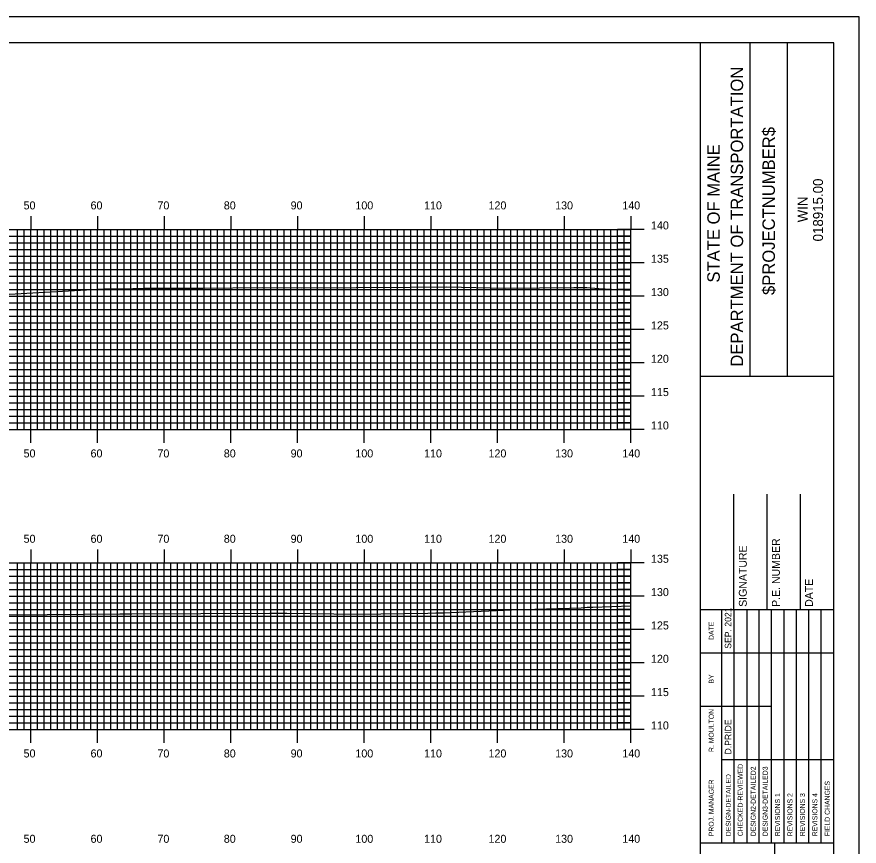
# Model space of a CAD drawing. Extents: x 852540 to 852884, y 364661 to 364881.
# Drawn here: x 852754.2 to 852880.5, y 364756.9 to 364881.3 of the extents above; entities that cross this region are included whole.
import ezdxf

# ---------------------------------------------------------------- set-up
doc = ezdxf.new("R2010")
doc.units = 0
for name, color, linetype in [('BORDER', 7, 'Continuous'), ('H_V ANNOTATION', 7, 'Continuous'), ('MAJOR', 7, 'Continuous'), ('MINOR', 7, 'Continuous'), ('PLOT BOUNDARY', 7, 'Continuous'), ('S_Roadway_Centerline', 7, 'Continuous')]:
    doc.layers.add(name, color=color, linetype=linetype)

msp = doc.modelspace()

# ---------------------------------------------------------------- linework, layer by layer
at = {"layer": 'BORDER'}
for p, q in [((852856.67, 364667.37), (852856.67, 364877.37)), ((852864.13, 364827.36), (852864.13, 364877.36)), ((852869.72, 364827.36), (852869.72, 364877.36)), ((852856.67, 364827.36), (852876.67, 364827.36)), ((852861.67, 364792.38), (852861.67, 364809.67)), ((852866.67, 364792.38), (852866.67, 364809.67)), ((852871.67, 364792.38), (852871.67, 364809.67)), ((852856.67, 364792.38), (852876.67, 364792.38)), ((852856.67, 364757.38), (852876.67, 364757.38)), ((852867.85, 364687.38), (852867.85, 364757.38))]:
    msp.add_line(p, q, dxfattribs=at)
msp.add_lwpolyline([(852556.67, 364667.37), (852876.67, 364667.37), (852876.67, 364877.37), (852556.67, 364877.37)], close=True, dxfattribs=at)
for points in [[(852859.9, 364785.88), (852859.9, 364792.38)], [(852861.76, 364757.38), (852861.76, 364792.38)], [(852863.63, 364792.38), (852863.63, 364757.38)], [(852865.49, 364757.38), (852865.49, 364792.38)], [(852867.35, 364757.38), (852867.35, 364792.38)], [(852869.22, 364757.38), (852869.22, 364792.38)], [(852871.08, 364757.38), (852871.08, 364792.38)], [(852872.94, 364757.38), (852872.94, 364792.38)], [(852874.81, 364757.38), (852874.81, 364792.38)], [(852859.9, 364757.38), (852859.9, 364790.96)], [(852856.67, 364785.88), (852876.67, 364785.88)], [(852856.67, 364777.88), (852859.9, 364777.88)], [(852859.9, 364777.88), (852867.35, 364777.88)], [(852859.9, 364769.88), (852876.67, 364769.88)]]:
    msp.add_lwpolyline(points, dxfattribs=at)
at = {"layer": 'MAJOR'}
for p, q in [((852756.27, 364851.37), (852756.27, 364849.37)), ((852766.27, 364851.37), (852766.27, 364849.37)), ((852776.27, 364851.37), (852776.27, 364849.37)), ((852786.27, 364851.37), (852786.27, 364849.37)), ((852796.27, 364851.37), (852796.27, 364849.37)), ((852806.27, 364851.37), (852806.27, 364849.37)), ((852816.27, 364851.37), (852816.27, 364849.37)), ((852826.27, 364851.37), (852826.27, 364849.37)), ((852836.27, 364851.37), (852836.27, 364849.37)), ((852846.27, 364851.37), (852846.27, 364849.37)), ((852566.27, 364849.37), (852846.27, 364849.37)), ((852566.27, 364849.37), (852846.27, 364849.37)), ((852756.27, 364819.37), (852756.27, 364849.37)), ((852766.27, 364819.37), (852766.27, 364849.37)), ((852776.27, 364819.37), (852776.27, 364849.37)), ((852786.27, 364819.37), (852786.27, 364849.37)), ((852796.27, 364819.37), (852796.27, 364849.37)), ((852806.27, 364819.37), (852806.27, 364849.37)), ((852816.27, 364819.37), (852816.27, 364849.37)), ((852826.27, 364819.37), (852826.27, 364849.37)), ((852836.27, 364819.37), (852836.27, 364849.37)), ((852848.27, 364849.37), (852844.26, 364849.37)), ((852846.27, 364819.37), (852846.27, 364849.37)), ((852846.27, 364819.37), (852846.27, 364849.37)), ((852566.27, 364844.37), (852846.27, 364844.37)), ((852848.27, 364844.37), (852844.26, 364844.37)), ((852566.27, 364839.37), (852846.27, 364839.37)), ((852848.27, 364839.37), (852844.26, 364839.37)), ((852566.27, 364834.37), (852846.27, 364834.37)), ((852848.27, 364834.37), (852844.26, 364834.37)), ((852566.27, 364829.37), (852846.27, 364829.37)), ((852848.27, 364829.37), (852844.26, 364829.37)), ((852566.27, 364824.37), (852846.27, 364824.37)), ((852848.27, 364824.37), (852844.26, 364824.37)), ((852566.27, 364819.37), (852846.27, 364819.37)), ((852566.27, 364819.37), (852846.27, 364819.37)), ((852756.27, 364817.37), (852756.27, 364819.37)), ((852766.27, 364817.37), (852766.27, 364819.37)), ((852776.27, 364817.37), (852776.27, 364819.37)), ((852786.27, 364817.37), (852786.27, 364819.37)), ((852796.27, 364817.37), (852796.27, 364819.37)), ((852806.27, 364817.37), (852806.27, 364819.37)), ((852816.27, 364817.37), (852816.27, 364819.37)), ((852826.27, 364817.37), (852826.27, 364819.37)), ((852836.27, 364817.37), (852836.27, 364819.37)), ((852848.27, 364819.37), (852844.26, 364819.37)), ((852846.27, 364817.37), (852846.27, 364819.37)), ((852756.27, 364801.37), (852756.27, 364799.37)), ((852766.27, 364801.37), (852766.27, 364799.37)), ((852776.27, 364801.37), (852776.27, 364799.37)), ((852786.27, 364801.37), (852786.27, 364799.37)), ((852796.27, 364801.37), (852796.27, 364799.37)), ((852806.27, 364801.37), (852806.27, 364799.37)), ((852816.27, 364801.37), (852816.27, 364799.37)), ((852826.27, 364801.37), (852826.27, 364799.37)), ((852836.27, 364801.37), (852836.27, 364799.37)), ((852846.27, 364801.37), (852846.27, 364799.37)), ((852566.27, 364799.37), (852846.27, 364799.37)), ((852566.27, 364799.37), (852846.27, 364799.37)), ((852756.27, 364774.37), (852756.27, 364799.37)), ((852766.27, 364774.37), (852766.27, 364799.37)), ((852776.27, 364774.37), (852776.27, 364799.37)), ((852786.27, 364774.37), (852786.27, 364799.37)), ((852796.27, 364774.37), (852796.27, 364799.37)), ((852806.27, 364774.37), (852806.27, 364799.37)), ((852816.27, 364774.37), (852816.27, 364799.37)), ((852826.27, 364774.37), (852826.27, 364799.37)), ((852836.27, 364774.37), (852836.27, 364799.37)), ((852848.27, 364799.37), (852844.26, 364799.37)), ((852846.27, 364774.37), (852846.27, 364799.37)), ((852846.27, 364774.37), (852846.27, 364799.37)), ((852566.27, 364794.37), (852846.27, 364794.37)), ((852848.27, 364794.37), (852844.26, 364794.37)), ((852566.27, 364789.37), (852846.27, 364789.37)), ((852848.27, 364789.37), (852844.26, 364789.37)), ((852566.27, 364784.37), (852846.27, 364784.37)), ((852848.27, 364784.37), (852844.26, 364784.37)), ((852566.27, 364779.37), (852846.27, 364779.37)), ((852848.27, 364779.37), (852844.26, 364779.37)), ((852566.27, 364774.37), (852846.27, 364774.37)), ((852566.27, 364774.37), (852846.27, 364774.37)), ((852756.27, 364772.37), (852756.27, 364774.37)), ((852766.27, 364772.37), (852766.27, 364774.37)), ((852776.27, 364772.37), (852776.27, 364774.37)), ((852786.27, 364772.37), (852786.27, 364774.37)), ((852796.27, 364772.37), (852796.27, 364774.37)), ((852806.27, 364772.37), (852806.27, 364774.37)), ((852816.27, 364772.37), (852816.27, 364774.37)), ((852826.27, 364772.37), (852826.27, 364774.37)), ((852836.27, 364772.37), (852836.27, 364774.37)), ((852848.27, 364774.37), (852844.26, 364774.37)), ((852846.27, 364772.37), (852846.27, 364774.37))]:
    msp.add_line(p, q, dxfattribs=at)
at = {"layer": 'MINOR'}
for p, q in [((852754.27, 364819.37), (852754.27, 364849.37)), ((852755.27, 364819.37), (852755.27, 364849.37)), ((852757.27, 364819.37), (852757.27, 364849.37)), ((852758.27, 364819.37), (852758.27, 364849.37)), ((852759.27, 364819.37), (852759.27, 364849.37)), ((852760.27, 364819.37), (852760.27, 364849.37)), ((852761.27, 364819.37), (852761.27, 364849.37)), ((852762.27, 364819.37), (852762.27, 364849.37)), ((852763.27, 364819.37), (852763.27, 364849.37)), ((852764.27, 364819.37), (852764.27, 364849.37)), ((852765.27, 364819.37), (852765.27, 364849.37)), ((852767.27, 364819.37), (852767.27, 364849.37)), ((852768.27, 364819.37), (852768.27, 364849.37)), ((852769.27, 364819.37), (852769.27, 364849.37)), ((852770.27, 364819.37), (852770.27, 364849.37)), ((852771.27, 364819.37), (852771.27, 364849.37)), ((852772.27, 364819.37), (852772.27, 364849.37)), ((852773.27, 364819.37), (852773.27, 364849.37)), ((852774.27, 364819.37), (852774.27, 364849.37)), ((852775.27, 364819.37), (852775.27, 364849.37)), ((852777.27, 364819.37), (852777.27, 364849.37)), ((852778.27, 364819.37), (852778.27, 364849.37)), ((852779.27, 364819.37), (852779.27, 364849.37)), ((852780.27, 364819.37), (852780.27, 364849.37)), ((852781.27, 364819.37), (852781.27, 364849.37)), ((852782.27, 364819.37), (852782.27, 364849.37)), ((852783.27, 364819.37), (852783.27, 364849.37)), ((852784.27, 364819.37), (852784.27, 364849.37)), ((852785.27, 364819.37), (852785.27, 364849.37)), ((852787.27, 364819.37), (852787.27, 364849.37)), ((852788.27, 364819.37), (852788.27, 364849.37)), ((852789.27, 364819.37), (852789.27, 364849.37)), ((852790.27, 364819.37), (852790.27, 364849.37)), ((852791.27, 364819.37), (852791.27, 364849.37)), ((852792.27, 364819.37), (852792.27, 364849.37)), ((852793.27, 364819.37), (852793.27, 364849.37)), ((852794.27, 364819.37), (852794.27, 364849.37)), ((852795.27, 364819.37), (852795.27, 364849.37)), ((852797.27, 364819.37), (852797.27, 364849.37)), ((852798.27, 364819.37), (852798.27, 364849.37)), ((852799.27, 364819.37), (852799.27, 364849.37)), ((852800.27, 364819.37), (852800.27, 364849.37)), ((852801.27, 364819.37), (852801.27, 364849.37)), ((852802.27, 364819.37), (852802.27, 364849.37)), ((852803.27, 364819.37), (852803.27, 364849.37)), ((852804.27, 364819.37), (852804.27, 364849.37)), ((852805.27, 364819.37), (852805.27, 364849.37)), ((852807.27, 364819.37), (852807.27, 364849.37)), ((852808.27, 364819.37), (852808.27, 364849.37)), ((852809.27, 364819.37), (852809.27, 364849.37)), ((852810.27, 364819.37), (852810.27, 364849.37)), ((852811.27, 364819.37), (852811.27, 364849.37)), ((852812.27, 364819.37), (852812.27, 364849.37)), ((852813.27, 364819.37), (852813.27, 364849.37)), ((852814.27, 364819.37), (852814.27, 364849.37)), ((852815.27, 364819.37), (852815.27, 364849.37)), ((852817.27, 364819.37), (852817.27, 364849.37)), ((852818.27, 364819.37), (852818.27, 364849.37)), ((852819.27, 364819.37), (852819.27, 364849.37)), ((852820.27, 364819.37), (852820.27, 364849.37)), ((852821.27, 364819.37), (852821.27, 364849.37)), ((852822.27, 364819.37), (852822.27, 364849.37)), ((852823.27, 364819.37), (852823.27, 364849.37)), ((852824.27, 364819.37), (852824.27, 364849.37)), ((852825.27, 364819.37), (852825.27, 364849.37)), ((852827.27, 364819.37), (852827.27, 364849.37)), ((852828.27, 364819.37), (852828.27, 364849.37)), ((852829.27, 364819.37), (852829.27, 364849.37)), ((852830.27, 364819.37), (852830.27, 364849.37)), ((852831.27, 364819.37), (852831.27, 364849.37)), ((852832.27, 364819.37), (852832.27, 364849.37)), ((852833.27, 364819.37), (852833.27, 364849.37)), ((852834.27, 364819.37), (852834.27, 364849.37)), ((852835.27, 364819.37), (852835.27, 364849.37)), ((852837.27, 364819.37), (852837.27, 364849.37)), ((852838.27, 364819.37), (852838.27, 364849.37)), ((852839.27, 364819.37), (852839.27, 364849.37)), ((852840.27, 364819.37), (852840.27, 364849.37)), ((852841.27, 364819.37), (852841.27, 364849.37)), ((852842.27, 364819.37), (852842.27, 364849.37)), ((852843.27, 364819.37), (852843.27, 364849.37)), ((852844.27, 364819.37), (852844.27, 364849.37)), ((852845.27, 364819.37), (852845.27, 364849.37)), ((852566.27, 364848.37), (852846.27, 364848.37)), ((852846.27, 364848.37), (852844.26, 364848.37)), ((852566.27, 364847.37), (852846.27, 364847.37)), ((852846.27, 364847.37), (852844.26, 364847.37)), ((852566.27, 364846.37), (852846.27, 364846.37)), ((852846.27, 364846.37), (852844.26, 364846.37)), ((852566.27, 364845.37), (852846.27, 364845.37)), ((852846.27, 364845.37), (852844.26, 364845.37)), ((852566.27, 364843.37), (852846.27, 364843.37)), ((852846.27, 364843.37), (852844.26, 364843.37)), ((852566.27, 364842.37), (852846.27, 364842.37)), ((852846.27, 364842.37), (852844.26, 364842.37)), ((852566.27, 364841.37), (852846.27, 364841.37)), ((852846.27, 364841.37), (852844.26, 364841.37)), ((852566.27, 364840.37), (852846.27, 364840.37)), ((852846.27, 364840.37), (852844.26, 364840.37)), ((852566.27, 364838.37), (852846.27, 364838.37)), ((852846.27, 364838.37), (852844.26, 364838.37)), ((852566.27, 364837.37), (852846.27, 364837.37)), ((852846.27, 364837.37), (852844.26, 364837.37)), ((852566.27, 364836.37), (852846.27, 364836.37)), ((852846.27, 364836.37), (852844.26, 364836.37)), ((852566.27, 364835.37), (852846.27, 364835.37)), ((852846.27, 364835.37), (852844.26, 364835.37)), ((852566.27, 364833.37), (852846.27, 364833.37)), ((852846.27, 364833.37), (852844.26, 364833.37)), ((852566.27, 364832.37), (852846.27, 364832.37)), ((852846.27, 364832.37), (852844.26, 364832.37)), ((852566.27, 364831.37), (852846.27, 364831.37)), ((852846.27, 364831.37), (852844.26, 364831.37)), ((852566.27, 364830.37), (852846.27, 364830.37)), ((852846.27, 364830.37), (852844.26, 364830.37)), ((852566.27, 364828.37), (852846.27, 364828.37)), ((852846.27, 364828.37), (852844.26, 364828.37)), ((852566.27, 364827.37), (852846.27, 364827.37)), ((852846.27, 364827.37), (852844.26, 364827.37)), ((852566.27, 364826.37), (852846.27, 364826.37)), ((852566.27, 364825.37), (852846.27, 364825.37)), ((852846.27, 364826.37), (852844.26, 364826.37)), ((852846.27, 364825.37), (852844.26, 364825.37)), ((852566.27, 364823.37), (852846.27, 364823.37)), ((852846.27, 364823.37), (852844.26, 364823.37)), ((852566.27, 364822.37), (852846.27, 364822.37)), ((852846.27, 364822.37), (852844.26, 364822.37)), ((852566.27, 364821.37), (852846.27, 364821.37)), ((852566.27, 364820.37), (852846.27, 364820.37)), ((852846.27, 364821.37), (852844.26, 364821.37)), ((852846.27, 364820.37), (852844.26, 364820.37)), ((852754.27, 364774.37), (852754.27, 364799.37)), ((852755.27, 364774.37), (852755.27, 364799.37)), ((852757.27, 364774.37), (852757.27, 364799.37)), ((852758.27, 364774.37), (852758.27, 364799.37)), ((852759.27, 364774.37), (852759.27, 364799.37)), ((852760.27, 364774.37), (852760.27, 364799.37)), ((852761.27, 364774.37), (852761.27, 364799.37)), ((852762.27, 364774.37), (852762.27, 364799.37)), ((852763.27, 364774.37), (852763.27, 364799.37)), ((852764.27, 364774.37), (852764.27, 364799.37)), ((852765.27, 364774.37), (852765.27, 364799.37)), ((852767.27, 364774.37), (852767.27, 364799.37)), ((852768.27, 364774.37), (852768.27, 364799.37)), ((852769.27, 364774.37), (852769.27, 364799.37)), ((852770.27, 364774.37), (852770.27, 364799.37)), ((852771.27, 364774.37), (852771.27, 364799.37)), ((852772.27, 364774.37), (852772.27, 364799.37)), ((852773.27, 364774.37), (852773.27, 364799.37)), ((852774.27, 364774.37), (852774.27, 364799.37)), ((852775.27, 364774.37), (852775.27, 364799.37)), ((852777.27, 364774.37), (852777.27, 364799.37)), ((852778.27, 364774.37), (852778.27, 364799.37)), ((852779.27, 364774.37), (852779.27, 364799.37)), ((852780.27, 364774.37), (852780.27, 364799.37)), ((852781.27, 364774.37), (852781.27, 364799.37)), ((852782.27, 364774.37), (852782.27, 364799.37)), ((852783.27, 364774.37), (852783.27, 364799.37)), ((852784.27, 364774.37), (852784.27, 364799.37)), ((852785.27, 364774.37), (852785.27, 364799.37)), ((852787.27, 364774.37), (852787.27, 364799.37)), ((852788.27, 364774.37), (852788.27, 364799.37)), ((852789.27, 364774.37), (852789.27, 364799.37)), ((852790.27, 364774.37), (852790.27, 364799.37)), ((852791.27, 364774.37), (852791.27, 364799.37)), ((852792.27, 364774.37), (852792.27, 364799.37)), ((852793.27, 364774.37), (852793.27, 364799.37)), ((852794.27, 364774.37), (852794.27, 364799.37)), ((852795.27, 364774.37), (852795.27, 364799.37)), ((852797.27, 364774.37), (852797.27, 364799.37)), ((852798.27, 364774.37), (852798.27, 364799.37)), ((852799.27, 364774.37), (852799.27, 364799.37)), ((852800.27, 364774.37), (852800.27, 364799.37)), ((852801.27, 364774.37), (852801.27, 364799.37)), ((852802.27, 364774.37), (852802.27, 364799.37)), ((852803.27, 364774.37), (852803.27, 364799.37)), ((852804.27, 364774.37), (852804.27, 364799.37)), ((852805.27, 364774.37), (852805.27, 364799.37)), ((852807.27, 364774.37), (852807.27, 364799.37)), ((852808.27, 364774.37), (852808.27, 364799.37)), ((852809.27, 364774.37), (852809.27, 364799.37)), ((852810.27, 364774.37), (852810.27, 364799.37)), ((852811.27, 364774.37), (852811.27, 364799.37)), ((852812.27, 364774.37), (852812.27, 364799.37)), ((852813.27, 364774.37), (852813.27, 364799.37)), ((852814.27, 364774.37), (852814.27, 364799.37)), ((852815.27, 364774.37), (852815.27, 364799.37)), ((852817.27, 364774.37), (852817.27, 364799.37)), ((852818.27, 364774.37), (852818.27, 364799.37)), ((852819.27, 364774.37), (852819.27, 364799.37)), ((852820.27, 364774.37), (852820.27, 364799.37)), ((852821.27, 364774.37), (852821.27, 364799.37)), ((852822.27, 364774.37), (852822.27, 364799.37)), ((852823.27, 364774.37), (852823.27, 364799.37)), ((852824.27, 364774.37), (852824.27, 364799.37)), ((852825.27, 364774.37), (852825.27, 364799.37)), ((852827.27, 364774.37), (852827.27, 364799.37)), ((852828.27, 364774.37), (852828.27, 364799.37)), ((852829.27, 364774.37), (852829.27, 364799.37)), ((852830.27, 364774.37), (852830.27, 364799.37)), ((852831.27, 364774.37), (852831.27, 364799.37)), ((852832.27, 364774.37), (852832.27, 364799.37)), ((852833.27, 364774.37), (852833.27, 364799.37)), ((852834.27, 364774.37), (852834.27, 364799.37)), ((852835.27, 364774.37), (852835.27, 364799.37)), ((852837.27, 364774.37), (852837.27, 364799.37)), ((852838.27, 364774.37), (852838.27, 364799.37)), ((852839.27, 364774.37), (852839.27, 364799.37)), ((852840.27, 364774.37), (852840.27, 364799.37)), ((852841.27, 364774.37), (852841.27, 364799.37)), ((852842.27, 364774.37), (852842.27, 364799.37)), ((852843.27, 364774.37), (852843.27, 364799.37)), ((852844.27, 364774.37), (852844.27, 364799.37)), ((852845.27, 364774.37), (852845.27, 364799.37)), ((852566.27, 364798.37), (852846.27, 364798.37)), ((852846.27, 364798.37), (852844.26, 364798.37)), ((852566.27, 364797.37), (852846.27, 364797.37)), ((852566.27, 364796.37), (852846.27, 364796.37)), ((852846.27, 364797.37), (852844.26, 364797.37)), ((852846.27, 364796.37), (852844.26, 364796.37)), ((852566.27, 364795.37), (852846.27, 364795.37)), ((852846.27, 364795.37), (852844.26, 364795.37)), ((852566.27, 364793.37), (852846.27, 364793.37)), ((852846.27, 364793.37), (852844.26, 364793.37)), ((852566.27, 364792.37), (852846.27, 364792.37)), ((852566.27, 364791.37), (852846.27, 364791.37)), ((852846.27, 364792.37), (852844.26, 364792.37)), ((852846.27, 364791.37), (852844.26, 364791.37)), ((852566.27, 364790.37), (852846.27, 364790.37)), ((852846.27, 364790.37), (852844.26, 364790.37)), ((852566.27, 364788.37), (852846.27, 364788.37)), ((852846.27, 364788.37), (852844.26, 364788.37)), ((852566.27, 364787.37), (852846.27, 364787.37)), ((852566.27, 364786.37), (852846.27, 364786.37)), ((852846.27, 364787.37), (852844.26, 364787.37)), ((852846.27, 364786.37), (852844.26, 364786.37)), ((852566.27, 364785.37), (852846.27, 364785.37)), ((852846.27, 364785.37), (852844.26, 364785.37)), ((852566.27, 364783.37), (852846.27, 364783.37)), ((852846.27, 364783.37), (852844.26, 364783.37)), ((852566.27, 364782.37), (852846.27, 364782.37)), ((852566.27, 364781.37), (852846.27, 364781.37)), ((852846.27, 364782.37), (852844.26, 364782.37)), ((852846.27, 364781.37), (852844.26, 364781.37)), ((852566.27, 364780.37), (852846.27, 364780.37)), ((852846.27, 364780.37), (852844.26, 364780.37)), ((852566.27, 364778.37), (852846.27, 364778.37)), ((852846.27, 364778.37), (852844.26, 364778.37)), ((852566.27, 364777.37), (852846.27, 364777.37)), ((852566.27, 364776.37), (852846.27, 364776.37)), ((852846.27, 364777.37), (852844.26, 364777.37)), ((852846.27, 364776.37), (852844.26, 364776.37)), ((852566.27, 364775.37), (852846.27, 364775.37)), ((852846.27, 364775.37), (852844.26, 364775.37))]:
    msp.add_line(p, q, dxfattribs=at)
at = {"layer": 'PLOT BOUNDARY'}
msp.add_lwpolyline([(852540.48, 364661.25), (852880.48, 364661.25), (852880.48, 364881.25), (852540.48, 364881.25)], close=True, dxfattribs=at)
at = {"layer": 'S_Roadway_Centerline'}
for points in [[(852748.53, 364839.42), (852767.3, 364840.46), (852769.98, 364840.48), (852773.19, 364840.58), (852782.05, 364840.55), (852791, 364840.65), (852796.81, 364840.59), (852813.32, 364840.72), (852818.65, 364840.75), (852827.39, 364840.58), (852837.71, 364840.67), (852839.65, 364840.64), (852841.46, 364840.52), (852846.27, 364840.27)], [(852747.63, 364791.55), (852758.74, 364791.59), (852769.65, 364791.71), (852770.56, 364791.7), (852771.41, 364791.71), (852792.13, 364791.8), (852793.4, 364791.82), (852794.66, 364791.79), (852805.27, 364791.65), (852815.83, 364791.79), (852817.02, 364791.85), (852818.12, 364791.85), (852828.35, 364792.32), (852838.82, 364792.59), (852839.69, 364792.69), (852840.54, 364792.69), (852846.27, 364792.89)]]:
    msp.add_lwpolyline(points, dxfattribs=at)

# ---------------------------------------------------------------- texts
at = {"layer": 'BORDER'}
for s, height, p in [('DEPARTMENT OF TRANSPORTATION', 1.8635, (852863.08, 364828.78)), ('$PROJECTNUMBER$', 1.8635, (852867.85, 364839.53)), ('STATE OF MAINE', 1.8635, (852859.58, 364841.39)), ('018915.00', 1.491, (852875.06, 364847.57)), ('WIN', 1.491, (852872.74, 364850.43)), ('P.E. NUMBER', 1.1811, (852868.59, 364792.76)), ('SIGNATURE', 1.181, (852863.63, 364792.76)), ('DATE', 1.181, (852873.55, 364792.76)), ('SEP. 2021', 0.969, (852861.31, 364786.47)), ('DATE', 0.743, (852858.68, 364787.79)), ('BY', 0.743, (852858.68, 364781.25)), ('R. MOULTON', 0.745, (852858.68, 364770.98)), ('D.PRIDE', 0.969, (852861.31, 364770.62)), ('CHECKED-REVIEWED', 0.7455, (852863.03, 364758.35)), ('DESIGN-DETAILED', 0.7455, (852861.24, 364758.35)), ('DESIGN2-DETAILED2', 0.7455, (852864.97, 364758.35)), ('DESIGN3-DETAILED3', 0.7455, (852866.76, 364758.35)), ('PROJ. MANAGER', 0.7455, (852858.68, 364758.35)), ('FIELD CHANGES', 0.7455, (852876.07, 364758.35)), ('REVISIONS 1', 0.7455, (852868.62, 364758.35)), ('REVISIONS 2', 0.7455, (852870.48, 364758.35)), ('REVISIONS 3', 0.7455, (852872.35, 364758.35)), ('REVISIONS 4', 0.7455, (852874.21, 364758.35))]:
    msp.add_text(s, height=height, rotation=90, dxfattribs=at).set_placement(p)
at = {"layer": 'H_V ANNOTATION'}
for s, p in [('50', (852755.2, 364852.37)), ('60', (852765.24, 364852.37)), ('70', (852775.27, 364852.37)), ('80', (852785.22, 364852.37)), ('90', (852795.24, 364852.37)), ('100', (852804.95, 364852.37)), ('110', (852815.25, 364852.37)), ('120', (852824.91, 364852.37)), ('130', (852834.9, 364852.37)), ('140', (852844.97, 364852.37)), ('140', (852849.27, 364849.37)), ('135', (852849.27, 364844.37)), ('130', (852849.27, 364839.37)), ('125', (852849.27, 364834.37)), ('120', (852849.27, 364829.37)), ('115', (852849.27, 364824.37)), ('110', (852849.27, 364819.37)), ('50', (852755.2, 364815.17)), ('60', (852765.24, 364815.17)), ('70', (852775.27, 364815.17)), ('80', (852785.22, 364815.17)), ('90', (852795.24, 364815.17)), ('100', (852804.95, 364815.17)), ('110', (852815.25, 364815.17)), ('120', (852824.91, 364815.17)), ('130', (852834.9, 364815.17)), ('140', (852844.97, 364815.17)), ('50', (852755.2, 364802.37)), ('60', (852765.24, 364802.37)), ('70', (852775.27, 364802.37)), ('80', (852785.22, 364802.37)), ('90', (852795.24, 364802.37)), ('100', (852804.95, 364802.37)), ('110', (852815.25, 364802.37)), ('120', (852824.91, 364802.37)), ('130', (852834.9, 364802.37)), ('140', (852844.97, 364802.37)), ('135', (852849.27, 364799.37)), ('130', (852849.27, 364794.37)), ('125', (852849.27, 364789.37)), ('120', (852849.27, 364784.37)), ('115', (852849.27, 364779.37)), ('110', (852849.27, 364774.37)), ('50', (852755.2, 364770.17)), ('60', (852765.24, 364770.17)), ('70', (852775.27, 364770.17)), ('80', (852785.22, 364770.17)), ('90', (852795.24, 364770.17)), ('100', (852804.95, 364770.17)), ('110', (852815.25, 364770.17)), ('120', (852824.91, 364770.17)), ('130', (852834.9, 364770.17)), ('140', (852844.97, 364770.17)), ('50', (852755.2, 364757.37)), ('60', (852765.24, 364757.37)), ('70', (852775.27, 364757.37)), ('80', (852785.22, 364757.37)), ('90', (852795.24, 364757.37)), ('100', (852804.95, 364757.37)), ('110', (852815.25, 364757.37)), ('120', (852824.91, 364757.37)), ('130', (852834.9, 364757.37)), ('140', (852844.97, 364757.37))]:
    msp.add_text(s, height=1.2, dxfattribs=at).set_placement(p)

doc.saveas('drawing.dxf')
